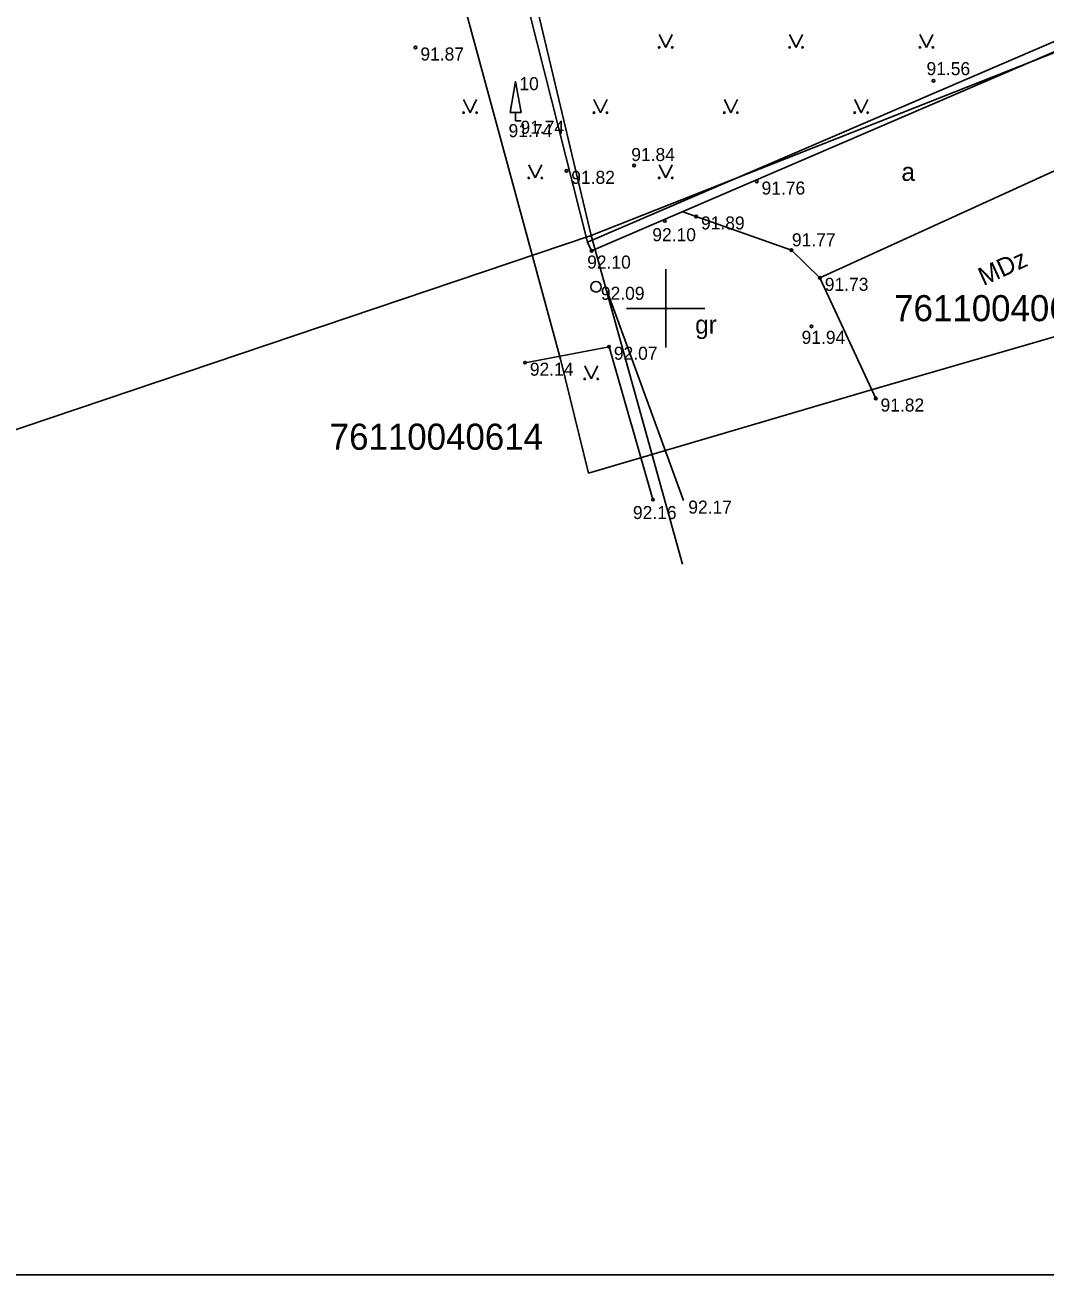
# Model space of a CAD drawing. Extents: x 634272 to 634544, y 247463 to 247653.
# Drawn here: x 634375.43 to 634414.55, y 247462.95 to 247510.86 of the extents above; entities that cross this region are included whole.
import ezdxf

# ---------------------------------------------------------------- set-up
doc = ezdxf.new("R2010")
doc.units = 0
for name, color, linetype in [('BUVE_EKAS_####_####_#', 7, 'Continuous'), ('BUVE_EKAS_RAKS_TKST_#', 7, 'Continuous'), ('CELI_CMAL_####_####_#', 7, 'Continuous'), ('CELI_CSEG_####_TKST_#', 7, 'Continuous'), ('GEOD_ELEM_####_####_#', 7, 'Continuous'), ('NORB_ELEM_####_####_#', 7, 'Continuous'), ('NORB_ZOGS_KONT_####_#', 7, 'Continuous'), ('NORB_ZOGS_SBST_####_#', 7, 'Continuous'), ('NORB_ZOGS_ZSTP_####_#', 7, 'Continuous'), ('RAMI_PLAN_####_TKST_#', 7, 'Continuous'), ('RAMI_UZMR_####_####_#', 7, 'Continuous'), ('RELJ_AATZ_####_TKST_#', 7, 'Continuous'), ('RELJ_ELEM_####_####_#', 7, 'Continuous'), ('ROBZ_KADS_####_TKST_#', 7, 'Continuous'), ('ROBZ_PROJ_####_####_#', 7, 'Continuous'), ('ROBZ_UZMR_####_####_#', 7, 'Continuous'), ('TERT_DIAM_####_TKST_#', 7, 'Continuous'), ('TERT_ELEM_####_####_#', 7, 'Continuous'), ('TERT_KRND_####_####_#', 7, 'Continuous')]:
    doc.layers.add(name, color=color, linetype=linetype)

msp = doc.modelspace()

# ---------------------------------------------------------------- linework, layer by layer
at = {"layer": 'BUVE_EKAS_####_####_#'}
msp.add_lwpolyline([(634408.055, 247496.543), (634405.917, 247501.17), (634417.83, 247506.605), (634420.287, 247501.019)], dxfattribs=at)
at = {"layer": 'CELI_CMAL_####_####_#'}
msp.add_lwpolyline([(634400.656, 247503.705), (634404.822, 247502.229), (634405.917, 247501.17)], dxfattribs=at)
at = {"layer": 'GEOD_ELEM_####_####_#'}
for p, q in [((634400, 247501.5), (634400, 247500)), ((634398.5, 247500), (634400, 247500)), ((634400, 247500), (634400, 247498.5)), ((634400, 247500), (634401.5, 247500))]:
    msp.add_line(p, q, dxfattribs=at)
at = {"layer": 'NORB_ELEM_####_####_#'}
msp.add_circle((634397.33, 247500.827), 0.202, dxfattribs=at)
at = {"layer": 'NORB_ZOGS_KONT_####_#'}
msp.add_lwpolyline([(634427.84, 247515.805), (634427.981, 247515.463), (634397.16, 247502.201), (634397.008, 247502.541), (634427.84, 247515.805)], dxfattribs=at)
at = {"layer": 'NORB_ZOGS_SBST_####_#'}
msp.add_lwpolyline([(634390.076, 247529.93), (634397.008, 247502.541)], dxfattribs=at)
at = {"layer": 'NORB_ZOGS_ZSTP_####_#'}
msp.add_lwpolyline([(634394.605, 247497.917), (634397.828, 247498.529), (634399.512, 247492.669)], dxfattribs=at)
at = {"layer": 'RAMI_PLAN_####_TKST_#'}
msp.add_lwpolyline([(634272.074, 247653.005), (634543.915, 247653.005), (634543.915, 247462.947), (634272.074, 247462.947)], close=True, dxfattribs=at)
at = {"layer": 'RAMI_UZMR_####_####_#'}
msp.add_lwpolyline([(634466.614, 247558.36), (634469.076, 247546.545), (634471.781, 247533.982), (634471.429, 247521.859), (634457.577, 247518.735), (634456.257, 247517.942), (634433.742, 247506.986), (634428.158, 247503.509), (634420.457, 247500.517), (634407.71, 247496.821), (634397.043, 247493.687), (634395.968, 247498.053), (634390.559, 247517.942), (634387.41, 247527.318), (634427.834, 247538.059), (634425.364, 247546.393), (634376.048, 247532.596), (634371.988, 247530.992)], dxfattribs=at)
at = {"layer": 'RELJ_ELEM_####_####_#'}
for centre in [(634390.407, 247509.999), (634410.271, 247508.718), (634396.194, 247505.271), (634398.788, 247505.478), (634403.492, 247504.86), (634399.965, 247503.348), (634401.17, 247503.523), (634404.822, 247502.229), (634397.16, 247502.201), (634405.917, 247501.17), (634405.596, 247499.309), (634397.828, 247498.529), (634394.605, 247497.917), (634408.055, 247496.543), (634399.512, 247492.669)]:
    msp.add_circle(centre, 0.05, dxfattribs=at)
at = {"layer": 'ROBZ_PROJ_####_####_#'}
for points in [[(634393.309, 247518.933), (634397.146, 247502.796)], [(634397.146, 247502.796), (634365.008, 247491.96)]]:
    msp.add_lwpolyline(points, dxfattribs=at)
at = {"layer": 'ROBZ_UZMR_####_####_#'}
for points in [[(634397.146, 247502.796), (634416.541, 247510.45)], [(634400.643, 247490.2), (634397.146, 247502.796)]]:
    msp.add_lwpolyline(points, dxfattribs=at)
at = {"layer": 'TERT_ELEM_####_####_#'}
for p, q in [((634399.75, 247510.5), (634400, 247510)), ((634400, 247510), (634400.25, 247510.5)), ((634404.75, 247510.5), (634405, 247510)), ((634405, 247510), (634405.25, 247510.5)), ((634409.75, 247510.5), (634410, 247510)), ((634410, 247510), (634410.25, 247510.5)), ((634392.25, 247508), (634392.5, 247507.5)), ((634392.5, 247507.5), (634392.75, 247508)), ((634397.25, 247508), (634397.5, 247507.5)), ((634397.5, 247507.5), (634397.75, 247508)), ((634402.25, 247508), (634402.5, 247507.5)), ((634402.5, 247507.5), (634402.75, 247508)), ((634407.25, 247508), (634407.5, 247507.5)), ((634407.5, 247507.5), (634407.75, 247508)), ((634394.246, 247507.19), (634394.246, 247507.51)), ((634394.246, 247507.19), (634394.456, 247507.19)), ((634394.75, 247505.5), (634395, 247505)), ((634395, 247505), (634395.25, 247505.5)), ((634399.75, 247505.5), (634400, 247505)), ((634400, 247505), (634400.25, 247505.5)), ((634396.896, 247497.797), (634397.146, 247497.297)), ((634397.146, 247497.297), (634397.396, 247497.797))]:
    msp.add_line(p, q, dxfattribs=at)
msp.add_lwpolyline([(634394.036, 247507.51), (634394.456, 247507.51), (634394.246, 247508.69)], close=True, dxfattribs=at)
for centre, radius in [((634399.75, 247510), 0.028), ((634400.25, 247510), 0.0263), ((634404.75, 247510), 0.028), ((634405.25, 247510), 0.0263), ((634409.75, 247510), 0.028), ((634410.25, 247510), 0.0263), ((634392.25, 247507.5), 0.028), ((634392.75, 247507.5), 0.0263), ((634397.25, 247507.5), 0.028), ((634397.75, 247507.5), 0.0263), ((634402.25, 247507.5), 0.028), ((634402.75, 247507.5), 0.0263), ((634407.25, 247507.5), 0.028), ((634407.75, 247507.5), 0.0263), ((634394.75, 247505), 0.028), ((634395.25, 247505), 0.0263), ((634399.75, 247505), 0.028), ((634400.25, 247505), 0.0263), ((634396.895, 247497.296), 0.028), ((634397.395, 247497.296), 0.0263)]:
    msp.add_circle(centre, radius, dxfattribs=at)
at = {"layer": 'TERT_KRND_####_####_#'}
msp.add_lwpolyline([(634400.682, 247492.631), (634397.751, 247500.66)], dxfattribs=at)

# ---------------------------------------------------------------- texts
at = {"layer": 'BUVE_EKAS_RAKS_TKST_#'}
msp.add_text('MDz', height=0.7, rotation=24.5236, dxfattribs=at).set_placement((634412.188, 247500.851))
at = {"layer": 'CELI_CSEG_####_TKST_#'}
for s, p in [('a', (634409.04, 247504.884)), ('gr', (634401.13, 247499.03))]:
    msp.add_text(s, height=0.7, dxfattribs=at).set_placement(p)
at = {"layer": 'RELJ_AATZ_####_TKST_#'}
for s, p in [(' 91.87', (634390.407, 247509.499)), (' 91.56', (634409.818, 247508.938)), (' 91.74', (634393.788, 247506.562)), (' 91.74', (634394.246, 247506.69)), (' 91.84', (634398.495, 247505.646)), (' 91.82', (634396.194, 247504.771)), (' 91.76', (634403.492, 247504.36)), (' 91.89', (634401.17, 247503.023)), (' 92.10', (634399.302, 247502.573)), (' 91.77', (634404.657, 247502.376)), (' 92.10', (634396.804, 247501.523)), (' 91.73', (634405.917, 247500.67)), (' 92.09', (634397.33, 247500.327)), (' 91.94', (634405.028, 247498.638)), (' 92.07', (634397.828, 247498.029)), (' 92.14', (634394.605, 247497.417)), (' 91.82', (634408.055, 247496.043)), (' 92.16', (634398.559, 247491.923)), (' 92.17', (634400.682, 247492.131))]:
    msp.add_text(s, height=0.5, dxfattribs=at).set_placement(p)
at = {"layer": 'ROBZ_KADS_####_TKST_#'}
for s, p in [('76110040611', (634408.763, 247499.507)), ('76110040614', (634387.115, 247494.579))]:
    msp.add_text(s, height=1, dxfattribs=at).set_placement(p)
at = {"layer": 'TERT_DIAM_####_TKST_#'}
msp.add_text('10', height=0.5, dxfattribs=at).set_placement((634394.39, 247508.362))

doc.saveas('drawing.dxf')
